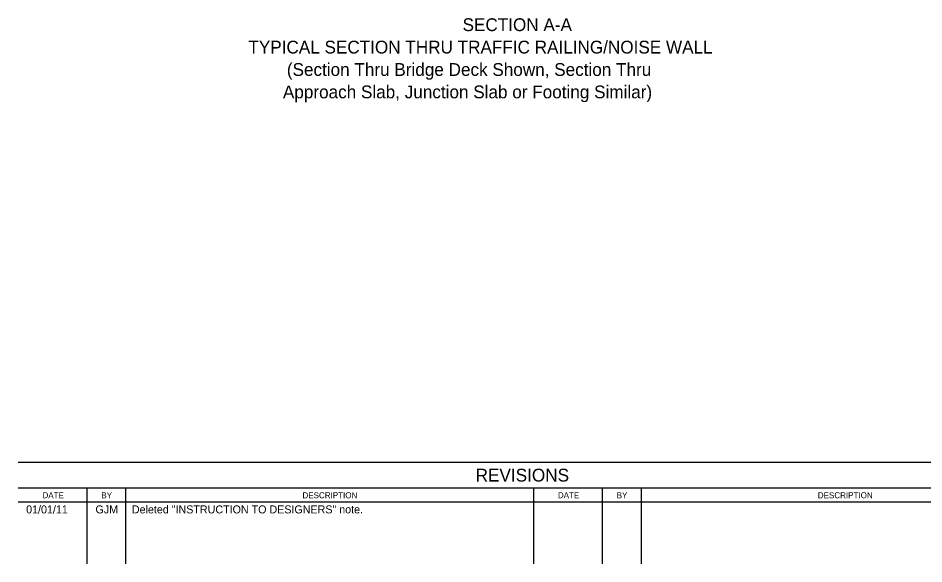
# Model space of a CAD drawing. Extents: x 120632.7 to 120668.8, y 120715.7 to 120740.6.
# Drawn here: x 120632.71 to 120641.76, y 120715.72 to 120721.18 of the extents above; entities that cross this region are included whole.
import ezdxf

# ---------------------------------------------------------------- set-up
doc = ezdxf.new("R2010")
doc.units = 0
for name, color, linetype in [('Border', 7, 'Continuous'), ('Dimension', 7, 'Continuous'), ('TextStructures', 7, 'Continuous')]:
    doc.layers.add(name, color=color, linetype=linetype)

msp = doc.modelspace()

# ---------------------------------------------------------------- linework, layer by layer
at = {"layer": 'Border'}
for p, q in [((120643.0132, 120716.7398), (120632.7073, 120716.7398)), ((120643.0132, 120716.4822), (120632.7073, 120716.4822)), ((120633.3957, 120716.4822), (120633.3957, 120715.7248)), ((120633.7824, 120716.4822), (120633.7824, 120715.7248)), ((120637.8604, 120716.4822), (120637.8604, 120715.7248)), ((120638.5487, 120716.4822), (120638.5487, 120715.7248)), ((120638.9355, 120716.4822), (120638.9355, 120715.7248)), ((120632.7073, 120716.3457), (120643.0132, 120716.3457))]:
    msp.add_line(p, q, dxfattribs=at)

# ---------------------------------------------------------------- texts
at = {"layer": 'Dimension'}
for s, p in [('SECTION A-A', (120637.1514, 120721.0522)), ('TYPICAL SECTION THRU TRAFFIC RAILING/NOISE WALL', (120635.0101, 120720.8282)), ('(Section Thru Bridge Deck Shown, Section Thru ', (120635.3945, 120720.6042)), ('Approach Slab, Junction Slab or Footing Similar)', (120635.3551, 120720.3802))]:
    msp.add_text(s, height=0.128, dxfattribs=at).set_placement(p)
at = {"layer": 'TextStructures'}
for s, height, p in [('REVISIONS', 0.12835, (120637.2817, 120716.548)), ('BY', 0.06005, (120633.5394, 120716.381)), ('BY', 0.06005, (120638.6925, 120716.381)), ('01/01/11', 0.08, (120632.7875, 120716.2295)), ('GJM', 0.08, (120633.4811, 120716.2295)), ('Deleted "INSTRUCTION TO DESIGNERS" note.', 0.08, (120633.845, 120716.2295))]:
    msp.add_text(s, height=height, dxfattribs=at).set_placement(p)
for s, height, rotation, p in [('DATE', 0.05978, 359.86925, (120632.9516, 120716.3814)), ('DESCRIPTION', 0.060035, 0.04975, (120635.5505, 120716.3808)), ('DATE', 0.05978, 359.86925, (120638.1046, 120716.3814)), ('DESCRIPTION', 0.060035, 0.04975, (120640.7036, 120716.3808))]:
    msp.add_text(s, height=height, rotation=rotation, dxfattribs=at).set_placement(p)

doc.saveas('drawing.dxf')
